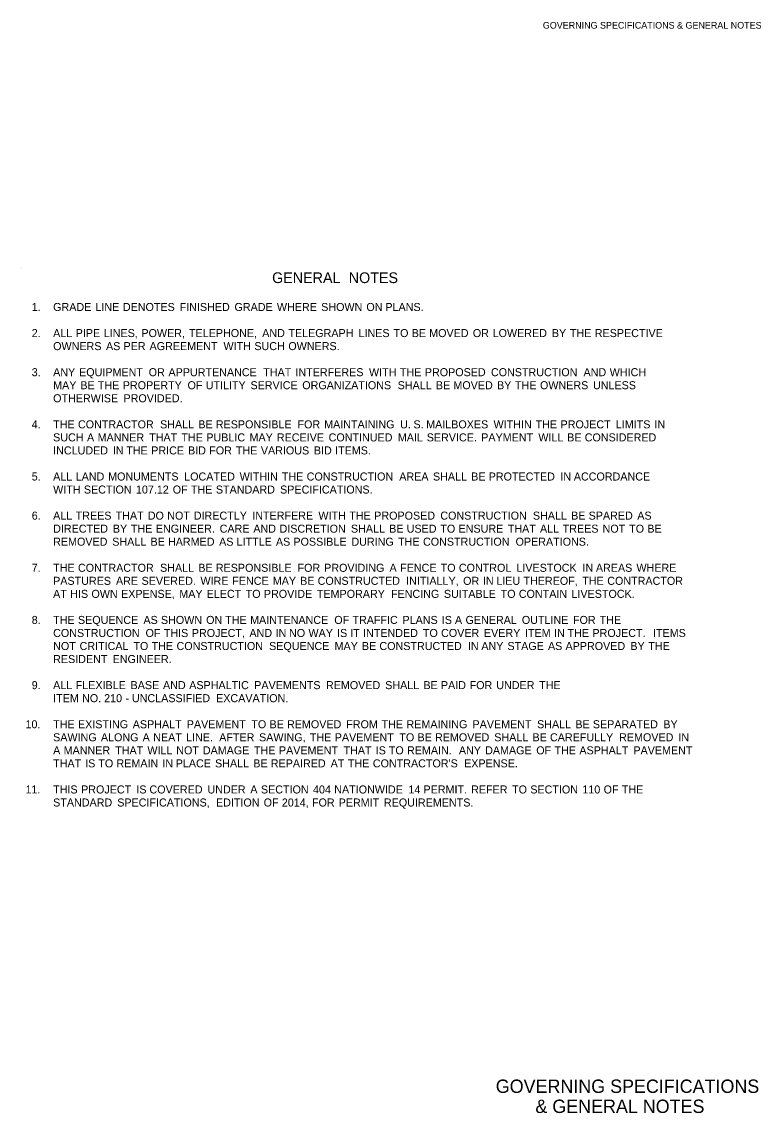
# Model space of a CAD drawing. Extents: x 194 to 1654, y 38 to 1017.
# Drawn here: x 991 to 1654, y 38 to 1017 of the extents above; entities that cross this region are included whole.
import ezdxf

# ---------------------------------------------------------------- set-up
doc = ezdxf.new("R2010")
doc.units = 0
for name, color, linetype in [('Default', 7, 'Continuous'), ('R_Annotation', 7, 'Continuous'), ('R_Border', 7, 'Continuous'), ('R_No Plot', 7, 'Continuous')]:
    doc.layers.add(name, color=color, linetype=linetype)

msp = doc.modelspace()

# ---------------------------------------------------------------- linework, layer by layer
at = {"layer": 'R_No Plot'}
msp.add_line((990.64, 795.13), (990.64, 795.13), dxfattribs=at)

# ---------------------------------------------------------------- texts
at = {"layer": 'Default'}
for s, height, p in [('GENERAL', 9.6, (1215.08, 782.43)), (' NOTES', 9.6, (1280.27, 782.43)), ('1.', 7.2, (999.51, 757.37)), ('GRADE', 7.2, (1018.72, 757.37)), (' LINE', 7.2, (1053.96, 757.37)), (' DENOTES', 7.2, (1078.58, 757.37)), (' FINISHED', 7.2, (1129.49, 757.37)), (' GRADE', 7.2, (1178.69, 757.37)), (' WHERE', 7.2, (1216.73, 757.37)), (' SHOWN', 7.2, (1256.44, 757.37)), (' ON', 7.2, (1296.97, 757.37)), (' PLANS.', 7.2, (1314.03, 757.37)), ('2.', 7.2, (999.51, 733.97)), ('ALL', 7.2, (1018.72, 733.97)), (' PIPE', 7.2, (1036.26, 733.97)), (' LINES,', 7.2, (1061.44, 733.97)), (' POWER,', 7.2, (1095.21, 733.97)), (' TELEPHONE,', 7.2, (1137.91, 733.97)), (' AND', 7.2, (1203.54, 733.97)), (' TELEGRAPH', 7.2, (1227.04, 733.97)), (' LINES', 7.2, (1289.97, 733.97)), (' TO', 7.2, (1321.31, 733.97)), (' BE', 7.2, (1337.62, 733.97)), (' MOVED', 7.2, (1353.3, 733.97)), (' OR', 7.2, (1392.45, 733.97)), (' LOWERED', 7.2, (1410.2, 733.97)), (' BY', 7.2, (1463.32, 733.97)), (' THE', 7.2, (1479.46, 733.97)), (' RESPECTIVE', 7.2, (1501.84, 733.97)), ('OWNERS', 7.2, (1018.72, 722.27)), (' AS', 7.2, (1063.47, 722.27)), (' PER', 7.2, (1079.16, 722.27)), (' AGREEMENT', 7.2, (1102.5, 722.27)), (' WITH', 7.2, (1168.82, 722.27)), (' SUCH', 7.2, (1196.5, 722.27)), (' OWNERS.', 7.2, (1226.99, 722.27)), ('3.', 7.2, (999.51, 698.87)), ('ANY', 7.2, (1018.72, 698.87)), (' EQUIPMENT', 7.2, (1039.33, 698.87)), (' OR', 7.2, (1101.73, 698.87)), (' APPURTENANCE', 7.2, (1119.48, 698.87)), (' THAT', 7.2, (1204.48, 698.87)), (' INTERFERES', 7.2, (1233.34, 698.87)), (' WITH', 7.2, (1299.34, 698.87)), (' THE', 7.2, (1327.02, 698.87)), (' PROPOSED', 7.2, (1349.4, 698.87)), (' CONSTRUCTION', 7.2, (1408.68, 698.87)), (' AND', 7.2, (1491.7, 698.87)), (' WHICH', 7.2, (1515.2, 698.87)), ('MAY', 7.2, (1018.72, 687.17)), (' BE', 7.2, (1040.45, 687.17)), (' THE', 7.2, (1056.12, 687.17)), (' PROPERTY', 7.2, (1078.5, 687.17)), (' OF', 7.2, (1136.57, 687.17)), (' UTILITY', 7.2, (1152.87, 687.17)), (' SERVICE', 7.2, (1193.04, 687.17)), (' ORGANIZATIONS', 7.2, (1239.47, 687.17)), (' SHALL', 7.2, (1325.02, 687.17)), (' BE', 7.2, (1359.33, 687.17)), (' MOVED', 7.2, (1375.01, 687.17)), (' BY', 7.2, (1414.16, 687.17)), (' THE', 7.2, (1430.3, 687.17)), (' OWNERS', 7.2, (1452.68, 687.17)), (' UNLESS', 7.2, (1500.22, 687.17)), ('OTHERWISE', 7.2, (1018.72, 675.47)), (' PROVIDED.', 7.2, (1079.11, 675.47)), ('4.', 7.2, (999.51, 652.07)), ('THE', 7.2, (1018.72, 652.07)), (' CONTRACTOR', 7.2, (1038.31, 652.07)), (' SHALL', 7.2, (1111.95, 652.07)), (' BE', 7.2, (1146.26, 652.07)), (' RESPONSIBLE', 7.2, (1161.94, 652.07)), (' FOR', 7.2, (1235.2, 652.07)), (' MAINTAINING', 7.2, (1259.1, 652.07)), (' U.', 7.2, (1327.21, 652.07)), (' S.', 7.2, (1339.19, 652.07)), (' MAILBOXES', 7.2, (1350.61, 652.07)), (' WITHIN', 7.2, (1411.02, 652.07)), (' THE', 7.2, (1448.75, 652.07)), (' PROJECT', 7.2, (1471.13, 652.07)), (' LIMITS', 7.2, (1520.68, 652.07)), (' IN', 7.2, (1555.36, 652.07)), ('SUCH', 7.2, (1018.72, 640.37)), (' A', 7.2, (1046.42, 640.37)), (' MANNER', 7.2, (1055.94, 640.37)), (' THAT', 7.2, (1102.19, 640.37)), (' THE', 7.2, (1131.06, 640.37)), (' PUBLIC', 7.2, (1153.43, 640.37)), (' MAY', 7.2, (1192.17, 640.37)), (' RECEIVE', 7.2, (1216.69, 640.37)), (' CONTINUED', 7.2, (1263.11, 640.37)), (' MAIL', 7.2, (1325.18, 640.37)), (' SERVICE.', 7.2, (1351.09, 640.37)), (' PAYMENT', 7.2, (1399.97, 640.37)), (' WILL', 7.2, (1451.2, 640.37)), (' BE', 7.2, (1477.11, 640.37)), (' CONSIDERED', 7.2, (1492.78, 640.37)), ('INCLUDED', 7.2, (1018.72, 628.67)), (' IN', 7.2, (1069.61, 628.67)), (' THE', 7.2, (1081.64, 628.67)), (' PRICE', 7.2, (1104.02, 628.67)), (' BID', 7.2, (1137.02, 628.67)), (' FOR', 7.2, (1156.05, 628.67)), (' THE', 7.2, (1179.94, 628.67)), (' VARIOUS', 7.2, (1202.32, 628.67)), (' BID', 7.2, (1249.87, 628.67)), (' ITEMS.', 7.2, (1268.9, 628.67)), ('5.', 7.2, (999.51, 605.27)), ('ALL', 7.2, (1018.72, 605.27)), (' LAND', 7.2, (1036.26, 605.27)), (' MONUMENTS', 7.2, (1065.35, 605.27)), (' LOCATED', 7.2, (1133.57, 605.27)), (' WITHIN', 7.2, (1183.34, 605.27)), (' THE', 7.2, (1221.07, 605.27)), (' CONSTRUCTION', 7.2, (1243.45, 605.27)), (' AREA', 7.2, (1326.47, 605.27)), (' SHALL', 7.2, (1356.68, 605.27)), (' BE', 7.2, (1390.99, 605.27)), (' PROTECTED', 7.2, (1406.66, 605.27)), (' IN', 7.2, (1470.97, 605.27)), (' ACCORDANCE', 7.2, (1483, 605.27)), ('WITH', 7.2, (1018.72, 593.57)), (' SECTION', 7.2, (1043.61, 593.57)), (' 107.12', 7.2, (1090.3, 593.57)), (' OF', 7.2, (1123.31, 593.57)), (' THE', 7.2, (1139.62, 593.57)), (' STANDARD', 7.2, (1162, 593.57)), (' SPECIFICATIONS.', 7.2, (1219.6, 593.57)), ('6.', 7.2, (999.51, 570.17)), ('ALL', 7.2, (1018.72, 570.17)), (' TREES', 7.2, (1036.26, 570.17)), (' THAT', 7.2, (1072.07, 570.17)), (' DO', 7.2, (1100.93, 570.17)), (' NOT', 7.2, (1118.37, 570.17)), (' DIRECTLY', 7.2, (1142.2, 570.17)), (' INTERFERE', 7.2, (1194.66, 570.17)), (' WITH', 7.2, (1253.94, 570.17)), (' THE', 7.2, (1281.62, 570.17)), (' PROPOSED', 7.2, (1304, 570.17)), (' CONSTRUCTION', 7.2, (1363.28, 570.17)), (' SHALL', 7.2, (1446.3, 570.17)), (' BE', 7.2, (1480.61, 570.17)), (' SPARED', 7.2, (1496.29, 570.17)), (' AS', 7.2, (1539.92, 570.17)), ('DIRECTED', 7.2, (1018.72, 558.47)), (' BY', 7.2, (1069.61, 558.47)), (' THE', 7.2, (1085.75, 558.47)), (' ENGINEER.', 7.2, (1108.13, 558.47)), (' CARE', 7.2, (1165.39, 558.47)), (' AND', 7.2, (1195.6, 558.47)), (' DISCRETION', 7.2, (1219.1, 558.47)), (' SHALL', 7.2, (1283.11, 558.47)), (' BE', 7.2, (1317.42, 558.47)), (' USED', 7.2, (1333.1, 558.47)), (' TO', 7.2, (1363.31, 558.47)), (' ENSURE', 7.2, (1379.63, 558.47)), (' THAT', 7.2, (1423.81, 558.47)), (' ALL', 7.2, (1452.67, 558.47)), (' TREES', 7.2, (1473.01, 558.47)), (' NOT', 7.2, (1508.82, 558.47)), (' TO', 7.2, (1532.65, 558.47)), (' BE', 7.2, (1548.96, 558.47)), ('REMOVED', 7.2, (1018.72, 546.77)), (' SHALL', 7.2, (1069.05, 546.77)), (' BE', 7.2, (1103.36, 546.77)), (' HARMED', 7.2, (1119.04, 546.77)), (' AS', 7.2, (1164.9, 546.77)), (' LITTLE', 7.2, (1180.59, 546.77)), (' AS', 7.2, (1215.83, 546.77)), (' POSSIBLE', 7.2, (1231.52, 546.77)), (' DURING', 7.2, (1283.54, 546.77)), (' THE', 7.2, (1325.38, 546.77)), (' CONSTRUCTION', 7.2, (1347.76, 546.77)), (' OPERATIONS.', 7.2, (1430.78, 546.77)), ('7.', 7.2, (999.51, 523.37)), ('THE', 7.2, (1018.72, 523.37)), (' CONTRACTOR', 7.2, (1038.31, 523.37)), (' SHALL', 7.2, (1111.95, 523.37)), (' BE', 7.2, (1146.26, 523.37)), (' RESPONSIBLE', 7.2, (1161.94, 523.37)), (' FOR', 7.2, (1235.2, 523.37)), (' PROVIDING', 7.2, (1259.1, 523.37)), (' A', 7.2, (1317.72, 523.37)), (' FENCE', 7.2, (1327.24, 523.37)), (' TO', 7.2, (1363.6, 523.37)), (' CONTROL', 7.2, (1379.91, 523.37)), (' LIVESTOCK', 7.2, (1431.53, 523.37)), (' IN', 7.2, (1490.78, 523.37)), (' AREAS', 7.2, (1502.8, 523.37)), (' WHERE', 7.2, (1539.18, 523.37)), ('PASTURES', 7.2, (1018.72, 511.67)), (' ARE', 7.2, (1072.43, 511.67)), (' SEVERED.', 7.2, (1095.37, 511.67)), (' WIRE', 7.2, (1148.17, 511.67)), (' FENCE', 7.2, (1176.69, 511.67)), (' MAY', 7.2, (1213.05, 511.67)), (' BE', 7.2, (1237.57, 511.67)), (' CONSTRUCTED', 7.2, (1253.25, 511.67)), (' INITIALLY,', 7.2, (1332.64, 511.67)), (' OR', 7.2, (1383.73, 511.67)), (' IN', 7.2, (1401.48, 511.67)), (' LIEU', 7.2, (1413.51, 511.67)), (' THEREOF,', 7.2, (1437.85, 511.67)), (' THE', 7.2, (1490.62, 511.67)), (' CONTRACTOR', 7.2, (1513, 511.67)), ('AT', 7.2, (1018.72, 499.97)), (' HIS', 7.2, (1031.37, 499.97)), (' OWN', 7.2, (1050.41, 499.97)), (' EXPENSE,', 7.2, (1076.97, 499.97)), (' MAY', 7.2, (1129.19, 499.97)), (' ELECT', 7.2, (1153.71, 499.97)), (' TO', 7.2, (1188.73, 499.97)), (' PROVIDE', 7.2, (1205.05, 499.97)), (' TEMPORARY', 7.2, (1252.59, 499.97)), (' FENCING', 7.2, (1319.03, 499.97)), (' SUITABLE', 7.2, (1366.47, 499.97)), (' TO', 7.2, (1417.37, 499.97)), (' CONTAIN', 7.2, (1433.69, 499.97)), (' LIVESTOCK.', 7.2, (1480.93, 499.97)), ('8.', 7.2, (999.51, 476.57)), ('THE', 7.2, (1018.72, 476.57)), (' SEQUENCE', 7.2, (1038.31, 476.57)), (' AS', 7.2, (1097.03, 476.57)), (' SHOWN', 7.2, (1112.72, 476.57)), (' ON', 7.2, (1153.25, 476.57)), (' THE', 7.2, (1170.32, 476.57)), (' MAINTENANCE', 7.2, (1192.69, 476.57)), (' OF', 7.2, (1268.18, 476.57)), (' TRAFFIC', 7.2, (1284.48, 476.57)), (' PLANS', 7.2, (1329.35, 476.57)), (' IS', 7.2, (1364.61, 476.57)), (' A', 7.2, (1376.38, 476.57)), (' GENERAL', 7.2, (1385.9, 476.57)), (' OUTLINE', 7.2, (1436.42, 476.57)), (' FOR', 7.2, (1482.28, 476.57)), (' THE', 7.2, (1506.17, 476.57)), ('CONSTRUCTION', 7.2, (1018.72, 464.87)), (' OF', 7.2, (1098.94, 464.87)), (' THIS', 7.2, (1115.24, 464.87)), (' PROJECT,', 7.2, (1140.43, 464.87)), (' AND', 7.2, (1192.08, 464.87)), (' IN', 7.2, (1215.58, 464.87)), (' NO', 7.2, (1227.61, 464.87)), (' WAY', 7.2, (1245.04, 464.87)), (' IS', 7.2, (1270.68, 464.87)), (' IT', 7.2, (1282.45, 464.87)), (' INTENDED', 7.2, (1293.98, 464.87)), (' TO', 7.2, (1347.66, 464.87)), (' COVER', 7.2, (1363.97, 464.87)), (' EVERY', 7.2, (1402.41, 464.87)), (' ITEM', 7.2, (1439.24, 464.87)), (' IN', 7.2, (1465.31, 464.87)), (' THE', 7.2, (1477.34, 464.87)), (' PROJECT.', 7.2, (1499.72, 464.87)), ('  ITEMS', 7.2, (1551.38, 464.87)), ('NOT', 7.2, (1018.72, 453.17)), (' CRITICAL', 7.2, (1039.75, 453.17)), (' TO', 7.2, (1088.03, 453.17)), (' THE', 7.2, (1104.34, 453.17)), (' CONSTRUCTION', 7.2, (1126.72, 453.17)), (' SEQUENCE', 7.2, (1209.73, 453.17)), (' MAY', 7.2, (1268.46, 453.17)), (' BE', 7.2, (1292.98, 453.17)), (' CONSTRUCTED', 7.2, (1308.66, 453.17)), (' IN', 7.2, (1388.05, 453.17)), (' ANY', 7.2, (1400.08, 453.17)), (' STAGE', 7.2, (1423.48, 453.17)), (' AS', 7.2, (1459.85, 453.17)), (' APPROVED', 7.2, (1475.54, 453.17)), (' BY', 7.2, (1533.71, 453.17)), (' THE', 7.2, (1549.85, 453.17)), ('RESIDENT', 7.2, (1018.72, 441.47)), (' ENGINEER.', 7.2, (1069.39, 441.47)), ('9.', 7.2, (999.51, 418.07)), ('ALL', 7.2, (1018.72, 418.07)), (' FLEXIBLE', 7.2, (1036.26, 418.07)), (' BASE', 7.2, (1085.48, 418.07)), (' AND', 7.2, (1114.59, 418.07)), (' ASPHALTIC', 7.2, (1138.09, 418.07)), (' PAVEMENTS', 7.2, (1196.39, 418.07)), (' REMOVED', 7.2, (1260.72, 418.07)), (' SHALL', 7.2, (1313.84, 418.07)), (' BE', 7.2, (1348.15, 418.07)), (' PAID', 7.2, (1363.83, 418.07)), (' FOR', 7.2, (1389.57, 418.07)), (' UNDER', 7.2, (1413.46, 418.07)), (' THE', 7.2, (1451.89, 418.07)), ('ITEM', 7.2, (1018.72, 406.37)), (' NO.', 7.2, (1041.99, 406.37)), (' 210', 7.2, (1061.79, 406.37)), (' UNCLASSIFIED', 7.2, (1086.71, 406.37)), (' EXCAVATION.', 7.2, (1162.2, 406.37)), (' -', 7.2, (1080.88, 406.37)), ('10.', 7.2, (993.92, 382.97)), ('THE', 7.2, (1018.72, 382.97)), (' EXISTING', 7.2, (1038.31, 382.97)), (' ASPHALT', 7.2, (1087.43, 382.97)), (' PAVEMENT', 7.2, (1135.87, 382.97)), (' TO', 7.2, (1193.81, 382.97)), (' BE', 7.2, (1210.12, 382.97)), (' REMOVED', 7.2, (1225.8, 382.97)), (' FROM', 7.2, (1278.93, 382.97)), (' THE', 7.2, (1310.58, 382.97)), (' REMAINING', 7.2, (1332.96, 382.97)), (' PAVEMENT', 7.2, (1392.14, 382.97)), (' SHALL', 7.2, (1450.08, 382.97)), (' BE', 7.2, (1484.39, 382.97)), (' SEPARATED', 7.2, (1500.07, 382.97)), (' BY', 7.2, (1563.27, 382.97)), ('SAWING', 7.2, (1018.72, 371.27)), (' ALONG', 7.2, (1058.89, 371.27)), (' A', 7.2, (1096.27, 371.27)), (' NEAT', 7.2, (1105.79, 371.27)), (' LINE.', 7.2, (1135.22, 371.27)), ('  AFTER', 7.2, (1162.29, 371.27)), (' SAWING,', 7.2, (1200.72, 371.27)), (' THE', 7.2, (1246.22, 371.27)), (' PAVEMENT', 7.2, (1268.6, 371.27)), (' TO', 7.2, (1326.54, 371.27)), (' BE', 7.2, (1342.85, 371.27)), (' REMOVED', 7.2, (1358.53, 371.27)), (' SHALL', 7.2, (1411.66, 371.27)), (' BE', 7.2, (1445.97, 371.27)), (' CAREFULLY', 7.2, (1461.65, 371.27)), (' REMOVED', 7.2, (1523.63, 371.27)), (' IN', 7.2, (1576.75, 371.27)), ('A', 7.2, (1018.72, 359.57)), (' MANNER', 7.2, (1025.45, 359.57)), (' THAT', 7.2, (1071.7, 359.57)), (' WILL', 7.2, (1100.57, 359.57)), (' NOT', 7.2, (1126.47, 359.57)), (' DAMAGE', 7.2, (1150.3, 359.57)), (' THE', 7.2, (1196.16, 359.57)), (' PAVEMENT', 7.2, (1218.54, 359.57)), (' THAT', 7.2, (1276.48, 359.57)), (' IS', 7.2, (1305.34, 359.57)), (' TO', 7.2, (1317.11, 359.57)), (' REMAIN.', 7.2, (1333.43, 359.57)), ('  ANY', 7.2, (1377.27, 359.57)), (' DAMAGE', 7.2, (1403.46, 359.57)), (' OF', 7.2, (1449.33, 359.57)), (' THE', 7.2, (1465.63, 359.57)), (' ASPHALT', 7.2, (1488.01, 359.57)), (' PAVEMENT', 7.2, (1536.45, 359.57)), ('THAT', 7.2, (1018.72, 347.87)), (' IS', 7.2, (1044.79, 347.87)), (' TO', 7.2, (1056.56, 347.87)), (' REMAIN', 7.2, (1072.87, 347.87)), (' IN', 7.2, (1113.97, 347.87)), (' PLACE', 7.2, (1126, 347.87)), (' SHALL', 7.2, (1161.25, 347.87)), (' BE', 7.2, (1195.56, 347.87)), (' REPAIRED', 7.2, (1211.24, 347.87)), (' AT', 7.2, (1264.93, 347.87)), (' THE', 7.2, (1280.38, 347.87)), (" CONTRACTOR'S", 7.2, (1302.76, 347.87)), (' EXPENSE.', 7.2, (1384.64, 347.87)), ('11.', 7.2, (993.92, 324.47)), ('THIS', 7.2, (1018.72, 324.47)), (' PROJECT', 7.2, (1041.11, 324.47)), (' IS', 7.2, (1090.66, 324.47)), (' COVERED', 7.2, (1102.43, 324.47)), (' UNDER', 7.2, (1154.44, 324.47)), (' A', 7.2, (1192.88, 324.47)), (' SECTION', 7.2, (1202.4, 324.47)), (' 404', 7.2, (1249.09, 324.47)), (' NATIONWIDE', 7.2, (1268.17, 324.47)), (' 14', 7.2, (1334.7, 324.47)), (' PERMIT.', 7.2, (1348.19, 324.47)), (' REFER', 7.2, (1390.9, 324.47)), (' TO', 7.2, (1427.66, 324.47)), (' SECTION', 7.2, (1443.98, 324.47)), (' 110', 7.2, (1490.67, 324.47)), (' OF', 7.2, (1509.75, 324.47)), (' THE', 7.2, (1526.06, 324.47)), ('STANDARD', 7.2, (1018.72, 312.77)), (' SPECIFICATIONS,', 7.2, (1073.53, 312.77)), (' EDITION', 7.2, (1162.07, 312.77)), (' OF', 7.2, (1204.84, 312.77)), (' 2014,', 7.2, (1221.15, 312.77)), (' FOR', 7.2, (1248.21, 312.77)), (' PERMIT', 7.2, (1272.1, 312.77)), (' REQUIREMENTS.', 7.2, (1312.7, 312.77))]:
    msp.add_text(s, height=height, dxfattribs=at).set_placement(p)
at = {"layer": 'R_Annotation'}
for s, p in [('GOVERNING SPECIFICATIONS', (1415.71, 55.77)), ('& GENERAL NOTES', (1451.24, 37.77))]:
    msp.add_text(s, height=12, dxfattribs=at).set_placement(p)
at = {"layer": 'R_Border'}
msp.add_text('GOVERNING SPECIFICATIONS & GENERAL NOTES', height=6, dxfattribs=at).set_placement((1457.91, 1010.75))

doc.saveas('drawing.dxf')
